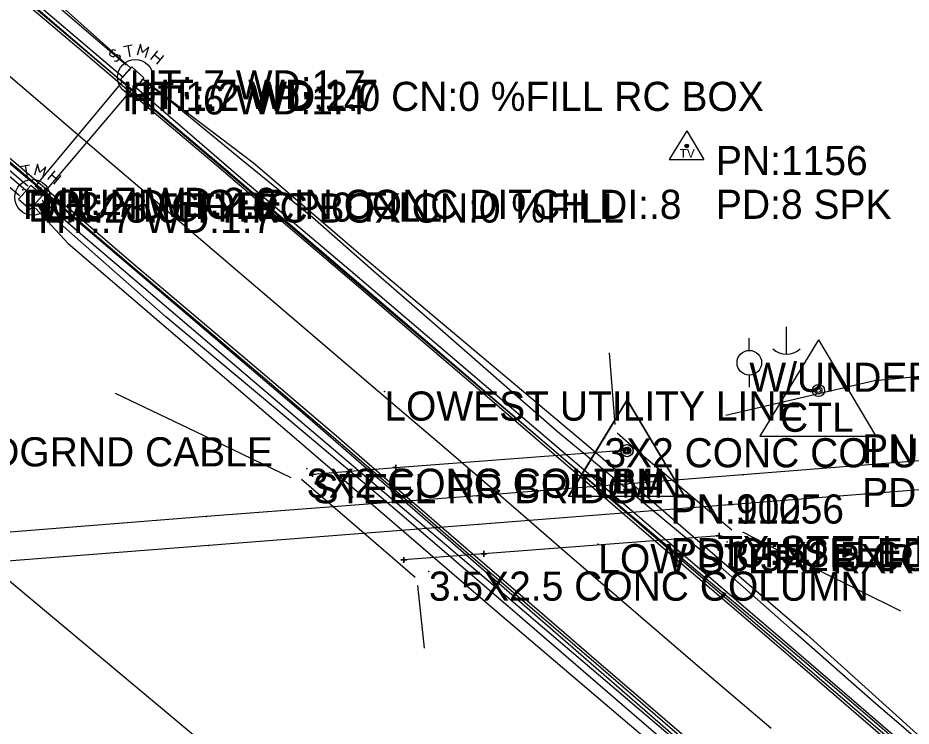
# Model space of a CAD drawing. Extents: x 878399 to 889864, y 1564003 to 1567413.
# Drawn here: x 884685 to 884838.2, y 1565440.6 to 1565562 of the extents above; entities that cross this region are included whole.
import ezdxf

# ---------------------------------------------------------------- set-up
doc = ezdxf.new("R2010")
doc.units = 0
for name, color, linetype in [('S_BRIDGE', 7, 'Continuous'), ('S_BRIDGE_ANNOT', 7, 'Continuous'), ('S_CATCH_BASIN_ANNOT', 7, 'Continuous'), ('S_CROSS_DRAIN', 7, 'Continuous'), ('S_CROSS_DRAIN_ANNOT', 7, 'Continuous'), ('S_DITCHLINE', 7, 'Continuous'), ('S_DRG_PT_SYM', 7, 'Continuous'), ('S_EDGE_CONCRETE', 7, 'Continuous'), ('S_EDGE_PAVEMENT', 7, 'Continuous'), ('S_ELECTRIC_UTILITIES_ANNOT', 7, 'Continuous'), ('S_FIBER_OPTIC_CABLE', 7, 'Continuous'), ('S_MISC_STRUCTURES_ANNOT', 7, 'Continuous'), ('S_MSC_PT_SYM', 7, 'Continuous'), ('S_PAVEMENT_CROWN', 7, 'Continuous'), ('S_PRIMARY_CTL', 7, 'Continuous'), ('S_PRIMARY_CTL_ANNOT', 7, 'Continuous'), ('S_RAILROAD', 7, 'Continuous'), ('S_SECONDARY_CTL', 7, 'Continuous'), ('S_SECONDARY_CTL_ANNOT', 7, 'Continuous'), ('S_SHOULDER', 7, 'Continuous'), ('S_STORM_SEWER', 7, 'Continuous'), ('S_STORM_SEWER_ANNOT', 7, 'Continuous'), ('S_STR_PT_SYM', 7, 'Continuous'), ('S_TELEPHONE_UTILITIES', 7, 'Continuous'), ('S_TELEPHONE_UTILITIES_ANNOT', 7, 'Continuous'), ('S_UTILITY_POLE', 7, 'Continuous'), ('S_UTL_PT_SYM', 7, 'Continuous'), ('S_WALL', 7, 'Continuous')]:
    doc.layers.add(name, color=color, linetype=linetype)

msp = doc.modelspace()

# ---------------------------------------------------------------- linework, layer by layer
at = {"layer": 'S_BRIDGE'}
for p, q in [((884749.84, 1565484.9), (884789.64, 1565487.95)), ((884735.58, 1565483.8), (884749.84, 1565484.9)), ((884805.3, 1565473.21), (884764.96, 1565470.14)), ((884764.96, 1565470.14), (884751.21, 1565469.07))]:
    msp.add_line(p, q, dxfattribs=at)
at = {"layer": 'S_CROSS_DRAIN'}
for p, q in [((884688.04, 1565533.14), (884702.96, 1565551.05)), ((884702.96, 1565551.05), (884704.57, 1565549.79)), ((884704.57, 1565549.79), (884689.4, 1565531.91)), ((884689.4, 1565531.91), (884688.04, 1565533.14))]:
    msp.add_line(p, q, dxfattribs=at)
at = {"layer": 'S_DITCHLINE'}
for points in [[(884703.6, 1565553.91), (884685.15, 1565569.81), (884674.64, 1565578.91)], [(884929.2, 1565361.71), (884912.86, 1565375.45), (884896.52, 1565389.2), (884880.31, 1565403.1), (884864.11, 1565417.01), (884847.9, 1565430.92), (884831.69, 1565444.83), (884818.34, 1565456.6), (884804.99, 1565468.36), (884791.26, 1565479.72), (884777.52, 1565491.09), (884767.03, 1565500.26), (884756.54, 1565509.43), (884746.04, 1565518.6), (884735.55, 1565527.77), (884723.63, 1565537.52), (884711.72, 1565547.27), (884706.92, 1565551.05)], [(884931.14, 1565322.32), (884915.28, 1565335.85), (884899.42, 1565349.39), (884882.54, 1565363.89), (884865.66, 1565378.39), (884848.78, 1565392.9), (884831.9, 1565407.4), (884813.4, 1565423.14), (884794.91, 1565438.87), (884783.2, 1565448.95), (884771.49, 1565459.02), (884759.78, 1565469.09), (884748.07, 1565479.17), (884729.25, 1565494.97), (884710.42, 1565510.77), (884693.84, 1565525.36), (884689.13, 1565529.56)], [(885174.2, 1565527.04), (885155.25, 1565525.71), (885136.3, 1565524.37), (885117.35, 1565523.04), (885098.4, 1565521.7), (885075.43, 1565519.72), (885052.47, 1565517.74), (885029.5, 1565515.76), (885006.54, 1565513.77), (884983.43, 1565512.24), (884960.32, 1565510.7), (884937.21, 1565509.17), (884914.1, 1565507.63), (884893.55, 1565505.67), (884873, 1565503.7), (884852.45, 1565501.74), (884831.9, 1565499.77), (884819.17, 1565496.81), (884806.44, 1565493.86)]]:
    msp.add_lwpolyline(points, dxfattribs=at)
at = {"layer": 'S_DRG_PT_SYM'}
for points in [[(884704.2, 1565553.02), (884704.2, 1565553.07), (884704.2, 1565553.02), (884704.15, 1565553.02), (884704.2, 1565553.02), (884704.2, 1565552.97), (884704.2, 1565553.02), (884704.25, 1565553.02)], [(884702.96, 1565551.05), (884702.96, 1565551.1), (884702.96, 1565551.05), (884702.91, 1565551.05), (884702.96, 1565551.05), (884702.96, 1565551), (884702.96, 1565551.05), (884703.01, 1565551.05)], [(884704.14, 1565550.45), (884704.14, 1565550.5), (884704.14, 1565550.45), (884704.08, 1565550.45), (884704.14, 1565550.45), (884704.14, 1565550.4), (884704.14, 1565550.45), (884704.19, 1565550.45)], [(884706.32, 1565551.39), (884706.32, 1565551.44), (884706.32, 1565551.39), (884706.27, 1565551.39), (884706.32, 1565551.39), (884706.32, 1565551.34), (884706.32, 1565551.39), (884706.37, 1565551.39)], [(884704.57, 1565549.79), (884704.57, 1565549.84), (884704.57, 1565549.79), (884704.51, 1565549.79), (884704.57, 1565549.79), (884704.57, 1565549.74), (884704.57, 1565549.79), (884704.61, 1565549.79)], [(884685.9, 1565532.54), (884685.9, 1565532.59), (884685.9, 1565532.54), (884685.85, 1565532.54), (884685.9, 1565532.54), (884685.9, 1565532.49), (884685.9, 1565532.54), (884685.95, 1565532.54)], [(884688.04, 1565533.14), (884688.04, 1565533.19), (884688.04, 1565533.14), (884687.99, 1565533.14), (884688.04, 1565533.14), (884688.04, 1565533.09), (884688.04, 1565533.14), (884688.09, 1565533.14)], [(884688.97, 1565532.88), (884688.97, 1565532.93), (884688.97, 1565532.88), (884688.92, 1565532.88), (884688.97, 1565532.88), (884688.97, 1565532.83), (884688.97, 1565532.88), (884689.02, 1565532.88)], [(884689.4, 1565531.91), (884689.4, 1565531.96), (884689.4, 1565531.91), (884689.35, 1565531.91), (884689.4, 1565531.91), (884689.4, 1565531.86), (884689.4, 1565531.91), (884689.45, 1565531.91)], [(884688.49, 1565530.11), (884688.49, 1565530.16), (884688.49, 1565530.11), (884688.44, 1565530.11), (884688.49, 1565530.11), (884688.49, 1565530.06), (884688.49, 1565530.11), (884688.54, 1565530.11)]]:
    msp.add_lwpolyline(points, dxfattribs=at)
at = {"layer": 'S_EDGE_CONCRETE'}
for points in [[(884323.93, 1565880.39), (884362.03, 1565848.01), (884400.08, 1565815.49), (884438.03, 1565782.92), (884475.84, 1565750.35), (884513.92, 1565717.85), (884552.01, 1565685.45), (884589.9, 1565652.9), (884627.72, 1565620.23), (884666.58, 1565587.18), (884704.34, 1565553.44)], [(884321.95, 1565878.07), (884359.86, 1565845.48), (884397.91, 1565812.97), (884436.05, 1565780.63), (884473.97, 1565748.16), (884511.98, 1565715.58), (884549.99, 1565683.11), (884587.82, 1565650.46), (884625.88, 1565618.07), (884664.43, 1565584.66), (884703.02, 1565551.9)], [(884515.49, 1565679.51), (884520.78, 1565674.96), (884543.23, 1565655.78), (884581.22, 1565623.28), (884619.31, 1565590.84), (884655, 1565560.28), (884686.74, 1565533.19)], [(884514.23, 1565678.05), (884518.85, 1565672.72), (884541.36, 1565653.58), (884579.74, 1565621.54), (884617.9, 1565589.19), (884653.7, 1565558.74), (884685.33, 1565531.53)], [(884706.6, 1565551.45), (884725.44, 1565537.13), (884744.17, 1565521.12), (884782.46, 1565488.91), (884820.33, 1565456.29), (884857.4, 1565422.83), (884893.19, 1565391.5), (884931.44, 1565358.94), (884969.96, 1565327.51), (885007.93, 1565294.95), (885045.65, 1565262.19), (885083.76, 1565229.98), (885121.86, 1565197.67), (885159.74, 1565165.3), (885198.19, 1565133.4), (885236.59, 1565102.25), (885296.12, 1565053.84), (885311.12, 1565043.35)], [(884705.4, 1565550.04), (884723.26, 1565534.58), (884742.1, 1565518.69), (884780.16, 1565486.23), (884818.14, 1565453.73), (884855.98, 1565421.17), (884892.08, 1565390.2), (884930.32, 1565357.68), (884968.08, 1565325.3), (885005.99, 1565292.69), (885044.06, 1565260.33), (885082.07, 1565227.99), (885120, 1565195.47), (885157.99, 1565163.2), (885196.4, 1565131.24), (885234.81, 1565099.94), (885295.36, 1565052.86), (885310.26, 1565042.23)], [(884689.18, 1565530.77), (884695.4, 1565525.38), (884733.42, 1565492.91), (884769.21, 1565462.51), (884807.31, 1565430.15), (884845.29, 1565397.58), (884883.12, 1565364.93), (884920.9, 1565332.67), (884959.15, 1565300.1), (884997.09, 1565267.66), (885035.26, 1565235.41), (885073.28, 1565202.9), (885111.19, 1565170.37), (885149.63, 1565138.23), (885187.82, 1565106.01), (885227.08, 1565074.25), (885266.64, 1565043.69), (885278.89, 1565034.31)], [(884688.03, 1565529.41), (884693.66, 1565523.34), (884731.61, 1565490.8), (884767.2, 1565460.17), (884805.29, 1565427.8), (884843.47, 1565395.44), (884881.16, 1565362.62), (884918.8, 1565330.29), (884957.02, 1565297.6), (884994.98, 1565265.2), (885032.99, 1565232.77), (885071.05, 1565200.29), (885109.01, 1565167.81), (885147.48, 1565135.65), (885185.66, 1565103.41), (885224.98, 1565071.52), (885264.55, 1565040.98), (885276.98, 1565031.83)]]:
    msp.add_lwpolyline(points, dxfattribs=at)
for points in [[(884704.78, 1565549.49), (884702.65, 1565551.39), (884704.56, 1565553.59), (884706.65, 1565551.72)], [(884689.24, 1565531.58), (884687.27, 1565533.25), (884685.15, 1565530.92), (884687.17, 1565529.21)]]:
    msp.add_lwpolyline(points, close=True, dxfattribs=at)
at = {"layer": 'S_EDGE_PAVEMENT'}
for points in [[(884673.76, 1565575.86), (884685.2, 1565566.15), (884696.63, 1565556.44), (884708.06, 1565546.72), (884719.51, 1565537.03), (884730.93, 1565527.29), (884742.33, 1565517.55), (884753.72, 1565507.79), (884765.12, 1565498.04), (884776.53, 1565488.26), (884787.91, 1565478.49), (884799.29, 1565468.72), (884810.66, 1565458.95), (884822.04, 1565449.18), (884833.38, 1565439.44), (884844.76, 1565429.68), (884856.14, 1565419.92), (884867.5, 1565410.14), (884878.86, 1565400.36), (884890.22, 1565390.58), (884901.62, 1565380.84), (884913.16, 1565370.98), (884924.56, 1565361.24)], [(884684.78, 1565565.87), (884696.21, 1565556.16), (884707.64, 1565546.44), (884719.09, 1565536.75), (884730.51, 1565527.01), (884741.91, 1565517.27), (884753.31, 1565507.51), (884764.7, 1565497.76), (884776.12, 1565487.98), (884787.5, 1565478.21), (884798.87, 1565468.44), (884810.25, 1565458.67), (884821.62, 1565448.9), (884832.97, 1565439.16), (884844.35, 1565429.4), (884855.73, 1565419.63), (884867.09, 1565409.85), (884878.45, 1565400.07), (884889.81, 1565390.29), (884901.21, 1565380.55), (884912.75, 1565370.69), (884924.15, 1565360.95)], [(884681.61, 1565539.03), (884693.05, 1565529.33), (884704.45, 1565519.58), (884715.9, 1565509.89), (884727.36, 1565500.21), (884738.77, 1565490.47), (884750.12, 1565480.67), (884761.46, 1565470.88), (884772.81, 1565461.08), (884784.18, 1565451.3), (884795.55, 1565441.52), (884806.91, 1565431.74), (884818.31, 1565421.91), (884829.66, 1565412.11), (884841.01, 1565402.32), (884852.37, 1565392.52), (884863.72, 1565382.73), (884875.07, 1565372.95), (884886.44, 1565363.18), (884897.65, 1565353.64), (884909.07, 1565343.93), (884920.49, 1565334.22)], [(884682.03, 1565539.31), (884693.47, 1565529.6), (884704.87, 1565519.86), (884716.32, 1565510.17), (884727.78, 1565500.49), (884739.19, 1565490.75), (884750.54, 1565480.95), (884761.87, 1565471.16), (884773.23, 1565461.36), (884784.59, 1565451.58), (884795.96, 1565441.8), (884807.33, 1565432.02), (884818.72, 1565422.19), (884830.07, 1565412.4), (884841.43, 1565402.6), (884852.78, 1565392.81), (884864.13, 1565383.02), (884875.48, 1565373.23), (884886.85, 1565363.46), (884898.06, 1565353.93), (884909.48, 1565344.22), (884920.89, 1565334.51)]]:
    msp.add_lwpolyline(points, dxfattribs=at)
at = {"layer": 'S_FIBER_OPTIC_CABLE'}
msp.add_line((884746.2, 1565413.17), (884630.03, 1565510.1), dxfattribs=at)
at = {"layer": 'S_MSC_PT_SYM'}
for points in [[(884785.6, 1565489.95), (884785.6, 1565490), (884785.6, 1565489.95), (884785.55, 1565489.95), (884785.6, 1565489.95), (884785.6, 1565489.9), (884785.6, 1565489.95), (884785.65, 1565489.95)], [(884734.59, 1565484.73), (884734.59, 1565484.78), (884734.59, 1565484.73), (884734.54, 1565484.73), (884734.59, 1565484.73), (884734.59, 1565484.68), (884734.59, 1565484.73), (884734.64, 1565484.73)], [(884809.34, 1565483.69), (884809.34, 1565483.74), (884809.34, 1565483.69), (884809.29, 1565483.69), (884809.34, 1565483.69), (884809.34, 1565483.64), (884809.34, 1565483.69), (884809.39, 1565483.69)], [(884763.8, 1565480.08), (884763.8, 1565480.13), (884763.8, 1565480.08), (884763.75, 1565480.08), (884763.8, 1565480.08), (884763.8, 1565480.03), (884763.8, 1565480.08), (884763.85, 1565480.08)], [(884809.99, 1565478.75), (884809.99, 1565478.8), (884809.99, 1565478.75), (884809.94, 1565478.75), (884809.99, 1565478.75), (884809.99, 1565478.7), (884809.99, 1565478.75), (884810.04, 1565478.75)], [(884717.39, 1565476.51), (884717.39, 1565476.56), (884717.39, 1565476.51), (884717.34, 1565476.51), (884717.39, 1565476.51), (884717.39, 1565476.46), (884717.39, 1565476.51), (884717.44, 1565476.51)], [(884763.99, 1565475.18), (884763.99, 1565475.23), (884763.99, 1565475.18), (884763.94, 1565475.18), (884763.99, 1565475.18), (884763.99, 1565475.13), (884763.99, 1565475.18), (884764.04, 1565475.18)], [(884806.66, 1565472.18), (884806.66, 1565472.23), (884806.66, 1565472.18), (884806.61, 1565472.18), (884806.66, 1565472.18), (884806.66, 1565472.13), (884806.66, 1565472.18), (884806.71, 1565472.18)], [(884717.78, 1565471.58), (884717.78, 1565471.63), (884717.78, 1565471.58), (884717.73, 1565471.58), (884717.78, 1565471.58), (884717.78, 1565471.53), (884717.78, 1565471.58), (884717.83, 1565471.58)], [(884784.56, 1565471.79), (884784.56, 1565471.84), (884784.56, 1565471.79), (884784.51, 1565471.79), (884784.56, 1565471.79), (884784.56, 1565471.74), (884784.56, 1565471.79), (884784.61, 1565471.79)], [(884755.52, 1565467.09), (884755.52, 1565467.14), (884755.52, 1565467.09), (884755.47, 1565467.09), (884755.52, 1565467.09), (884755.52, 1565467.04), (884755.52, 1565467.09), (884755.57, 1565467.09)]]:
    msp.add_lwpolyline(points, dxfattribs=at)
at = {"layer": 'S_PAVEMENT_CROWN'}
msp.add_lwpolyline([(884677.44, 1565557.27), (884688.85, 1565547.53), (884688.85, 1565547.53), (884700.26, 1565537.79), (884711.67, 1565528.05), (884711.67, 1565528.05), (884723.08, 1565518.31), (884734.49, 1565508.57), (884745.91, 1565498.84), (884757.32, 1565489.1), (884757.32, 1565489.1), (884768.69, 1565479.32), (884780.05, 1565469.52), (884791.41, 1565459.73), (884802.78, 1565449.96), (884814.18, 1565440.22)], dxfattribs=at)
at = {"layer": 'S_PRIMARY_CTL'}
for p, q in [((884822.31, 1565506.83), (884812.28, 1565490.32)), ((884822.31, 1565506.83), (884832.14, 1565490.32)), ((884789.45, 1565496.51), (884779.42, 1565479.99)), ((884789.53, 1565496.52), (884779.49, 1565480.01)), ((884789.45, 1565496.51), (884799.28, 1565479.99)), ((884789.53, 1565496.52), (884799.35, 1565480.01)), ((884812.28, 1565490.32), (884832.14, 1565490.32)), ((884779.42, 1565479.99), (884799.28, 1565479.99)), ((884779.49, 1565480.01), (884799.35, 1565480.01))]:
    msp.add_line(p, q, dxfattribs=at)
for centre, radius in [((884822.31, 1565498.13), 1.04), ((884822.31, 1565498.13), 0.609), ((884822.31, 1565498.13), 0.344), ((884789.45, 1565487.81), 1.04), ((884789.53, 1565487.82), 1.04), ((884789.45, 1565487.81), 0.609), ((884789.53, 1565487.82), 0.609), ((884789.45, 1565487.81), 0.344), ((884789.53, 1565487.82), 0.344)]:
    msp.add_circle(centre, radius, dxfattribs=at)
at = {"layer": 'S_RAILROAD'}
for p, q in [((884860, 1565487.69), (884809.34, 1565483.69)), ((884809.34, 1565483.69), (884763.8, 1565480.08)), ((884860.76, 1565482.78), (884809.99, 1565478.75)), ((884763.8, 1565480.08), (884717.39, 1565476.51)), ((884809.99, 1565478.75), (884763.99, 1565475.18)), ((884717.39, 1565476.51), (884681.18, 1565473.66)), ((884763.99, 1565475.18), (884717.78, 1565471.58)), ((884717.78, 1565471.58), (884681.7, 1565468.75))]:
    msp.add_line(p, q, dxfattribs=at)
at = {"layer": 'S_SECONDARY_CTL'}
for p, q in [((884799.74, 1565542.66), (884796.73, 1565537.71)), ((884799.74, 1565542.66), (884802.69, 1565537.71)), ((884796.73, 1565537.71), (884802.69, 1565537.71))]:
    msp.add_line(p, q, dxfattribs=at)
for radius in [0.311, 0.183, 0.103]:
    msp.add_circle((884799.74, 1565540.05), radius, dxfattribs=at)
at = {"layer": 'S_SHOULDER'}
for points in [[(884315.55, 1565882.9), (884321.54, 1565877.6), (884359.45, 1565845), (884397.59, 1565812.6), (884435.73, 1565780.26), (884473.65, 1565747.79), (884511.66, 1565715.22), (884549.66, 1565682.72), (884587.52, 1565650.1), (884625.56, 1565617.69), (884664.18, 1565584.36), (884702.58, 1565551.39), (884704.78, 1565549.31), (884722.81, 1565534.04), (884741.48, 1565517.97), (884779.63, 1565485.61), (884817.88, 1565453.42), (884855.77, 1565420.91), (884891.75, 1565389.81), (884929.91, 1565357.22)], [(884655.38, 1565560.72), (884687.38, 1565533.95), (884690.03, 1565531.77), (884696.22, 1565526.35), (884734.31, 1565493.96), (884769.75, 1565463.15), (884807.48, 1565430.34), (884845.42, 1565397.74), (884883.27, 1565365.1), (884921.11, 1565332.91)]]:
    msp.add_lwpolyline(points, dxfattribs=at)
at = {"layer": 'S_STORM_SEWER'}
for p, q in [((884686.78, 1565532.07), (884514.98, 1565679.93)), ((884701.39, 1565556.51), (884700.85, 1565556.12)), ((884701.81, 1565556.43), (884701.39, 1565556.51)), ((884703.13, 1565557.09), (884704.64, 1565557.36)), ((884703.91, 1565557.25), (884704.26, 1565555.31)), ((884707.82, 1565554.88), (884709.06, 1565556.36)), ((884700.85, 1565556.12), (884700.77, 1565555.74)), ((884700.77, 1565555.74), (884700.96, 1565555.47)), ((884700.96, 1565555.47), (884701.39, 1565555.35)), ((884701.39, 1565555.35), (884701.93, 1565555.7)), ((884701.93, 1565555.7), (884702.4, 1565555.62)), ((884702.47, 1565554.92), (884701.93, 1565554.54)), ((884702.4, 1565555.62), (884702.55, 1565555.35)), ((884702.55, 1565555.35), (884702.47, 1565554.92)), ((884708.48, 1565555.66), (884709.45, 1565554.85)), ((884710.03, 1565555.54), (884708.79, 1565554.07)), ((884701.93, 1565554.54), (884701.54, 1565554.61)), ((884685.5, 1565536.53), (884687.01, 1565536.8)), ((884686.27, 1565536.68), (884686.62, 1565534.74)), ((884690.19, 1565534.32), (884691.43, 1565535.79)), ((884690.85, 1565535.09), (884691.82, 1565534.28)), ((884692.4, 1565534.98), (884691.16, 1565533.5))]:
    msp.add_line(p, q, dxfattribs=at)
for points in [[(884706.93, 1565555.19), (884707.47, 1565557.05), (884706.43, 1565556.05), (884706.04, 1565557.48), (884705.5, 1565555.62)], [(884689.3, 1565534.63), (884689.84, 1565536.49), (884688.79, 1565535.48), (884688.41, 1565536.91), (884687.86, 1565535.05)]]:
    msp.add_lwpolyline(points, dxfattribs=at)
for centre in [(884705.17, 1565551.82), (884687.54, 1565531.25)]:
    msp.add_circle(centre, 3.05, dxfattribs=at)
at = {"layer": 'S_STR_PT_SYM'}
for points in [[(884789.64, 1565487.95), (884789.64, 1565488.45), (884789.64, 1565487.95), (884789.14, 1565487.95), (884789.64, 1565487.95), (884789.64, 1565487.45), (884789.64, 1565487.95), (884790.14, 1565487.95)], [(884749.84, 1565484.9), (884749.84, 1565485.4), (884749.84, 1565484.9), (884749.34, 1565484.9), (884749.84, 1565484.9), (884749.84, 1565484.4), (884749.84, 1565484.9), (884750.34, 1565484.9)], [(884735.58, 1565483.8), (884735.58, 1565484.3), (884735.58, 1565483.8), (884735.08, 1565483.8), (884735.58, 1565483.8), (884735.58, 1565483.3), (884735.58, 1565483.8), (884736.08, 1565483.8)], [(884805.3, 1565473.21), (884805.3, 1565473.71), (884805.3, 1565473.21), (884804.8, 1565473.21), (884805.3, 1565473.21), (884805.3, 1565472.71), (884805.3, 1565473.21), (884805.8, 1565473.21)], [(884764.96, 1565470.14), (884764.96, 1565470.64), (884764.96, 1565470.14), (884764.46, 1565470.14), (884764.96, 1565470.14), (884764.96, 1565469.64), (884764.96, 1565470.14), (884765.46, 1565470.14)], [(884751.21, 1565469.07), (884751.21, 1565469.57), (884751.21, 1565469.07), (884750.71, 1565469.07), (884751.21, 1565469.07), (884751.21, 1565468.57), (884751.21, 1565469.07), (884751.71, 1565469.07)]]:
    msp.add_lwpolyline(points, dxfattribs=at)
at = {"layer": 'S_TELEPHONE_UTILITIES'}
for p, q in [((884810.43, 1565504.97), (884810.43, 1565507.1)), ((884810.43, 1565500.75), (884810.43, 1565498.7))]:
    msp.add_line(p, q, dxfattribs=at)
msp.add_circle((884810.46, 1565502.89), 2.11, dxfattribs=at)
at = {"layer": 'S_UTILITY_POLE'}
msp.add_line((884816.77, 1565509.06), (884816.77, 1565504.33), dxfattribs=at)
msp.add_arc((884816.83, 1565507.76), 3.41, 226.3972, 313.6028, dxfattribs=at)
at = {"layer": 'S_UTL_PT_SYM'}
for points in [[(884705.09, 1565551.78), (884705.09, 1565551.83), (884705.09, 1565551.78), (884705.04, 1565551.78), (884705.09, 1565551.78), (884705.09, 1565551.73), (884705.09, 1565551.78), (884705.14, 1565551.78)], [(884686.78, 1565532.07), (884686.78, 1565532.12), (884686.78, 1565532.07), (884686.73, 1565532.07), (884686.78, 1565532.07), (884686.78, 1565532.02), (884686.78, 1565532.07), (884686.83, 1565532.07)], [(884687.68, 1565531.36), (884687.68, 1565531.41), (884687.68, 1565531.36), (884687.63, 1565531.36), (884687.68, 1565531.36), (884687.68, 1565531.31), (884687.68, 1565531.36), (884687.73, 1565531.36)], [(884747.88, 1565497.96), (884747.88, 1565498.01), (884747.88, 1565497.96), (884747.83, 1565497.96), (884747.88, 1565497.96), (884747.88, 1565497.91), (884747.88, 1565497.96), (884747.93, 1565497.96)]]:
    msp.add_lwpolyline(points, dxfattribs=at)
at = {"layer": 'S_WALL'}
for points in [[(884787.48, 1565492.29), (884786.48, 1565504.57)], [(884731.9, 1565483.17), (884716.84, 1565490.39), (884701.78, 1565497.61)], [(884787.8, 1565490.87), (884792.06, 1565487.12), (884807.46, 1565474.22)], [(884733.69, 1565482.95), (884749.32, 1565469.43), (884753.14, 1565466.15)], [(884809.28, 1565473.9), (884815.06, 1565470.92), (884836.39, 1565460.38)], [(884754.74, 1565453.94), (884753.64, 1565464.71)]]:
    msp.add_lwpolyline(points, dxfattribs=at)

# ---------------------------------------------------------------- texts
at = {"layer": 'S_BRIDGE_ANNOT'}
for s, p in [('STEEL RR BRIDGE', (884735.58, 1565478.8)), ('TY:STEEL RR RR BRIDGE', (884805.3, 1565468.21))]:
    msp.add_text(s, height=5, dxfattribs=at).set_placement(p)
at = {"layer": 'S_CATCH_BASIN_ANNOT'}
for s, p in [('HT:.7 WD:1.7', (884704.2, 1565548.02)), ('HT:.6 WD:1.4', (884704.14, 1565545.45)), ('HT:.7 WD:1.7', (884706.32, 1565546.39)), ('ROUND HOLE IN CONC DITCH DI:.8', (884685.9, 1565527.54)), ('HT:.7 WD:2.0', (884688.97, 1565527.88)), ('HT:.7 WD:1.7', (884688.49, 1565525.11))]:
    msp.add_text(s, height=5, dxfattribs=at).set_placement(p)
at = {"layer": 'S_CROSS_DRAIN_ANNOT'}
for s, p in [('HT:1.2 WD:2.0 CN:0 %FILL RC BOX', (884702.96, 1565546.05)), ('LN:23.5 TY:RC BOX CN:0 %FILL', (884689.4, 1565526.91))]:
    msp.add_text(s, height=5, dxfattribs=at).set_placement(p)
at = {"layer": 'S_ELECTRIC_UTILITIES_ANNOT'}
msp.add_text('LOWEST UTILITY LINE', height=5, dxfattribs=at).set_placement((884747.88, 1565492.96))
at = {"layer": 'S_MISC_STRUCTURES_ANNOT'}
for s, p in [('3X2 CONC COLUMN', (884785.6, 1565484.95)), ('3X2 CONC COLUMN', (884734.59, 1565479.73)), ('3.5X2.5 CONC COLUMN', (884806.66, 1565467.18)), ('LOW STEEL RXR BR 14.5 ABOVE HWY 82', (884784.56, 1565466.79)), ('3.5X2.5 CONC COLUMN', (884755.52, 1565462.09))]:
    msp.add_text(s, height=5, dxfattribs=at).set_placement(p)
at = {"layer": 'S_PRIMARY_CTL'}
for s, height, p in [('CTL', 5, (884815.73, 1565491.05)), ('TBM', 4.287, (884783.8, 1565480.42)), ('TBM', 4.287, (884783.87, 1565480.43))]:
    msp.add_text(s, height=height, rotation=360, dxfattribs=at).set_placement(p)
at = {"layer": 'S_PRIMARY_CTL_ANNOT'}
for s, p in [('PN:4', (884829.81, 1565485.63)), ('PD:ARDOT STD. MON. STAMPED PN:4', (884829.81, 1565478.13)), ('PN:11056', (884796.95, 1565475.31)), ('PN:902', (884797.03, 1565475.32)), ('PD:', (884796.95, 1565467.81)), ('PD:CHISELED SQUARE', (884797.03, 1565467.82))]:
    msp.add_text(s, height=5, dxfattribs=at).set_placement(p)
at = {"layer": 'S_SECONDARY_CTL'}
msp.add_text('TV', height=1.5, rotation=360, dxfattribs=at).set_placement((884798.54, 1565538.04))
at = {"layer": 'S_SECONDARY_CTL_ANNOT'}
for s, p in [('PN:1156', (884804.74, 1565535.05)), ('PD:8 SPK', (884804.74, 1565527.55))]:
    msp.add_text(s, height=5, dxfattribs=at).set_placement(p)
at = {"layer": 'S_STORM_SEWER_ANNOT'}
msp.add_text('DI:24 INCH RCP 0 FILL', height=5, dxfattribs=at).set_placement((884686.78, 1565527.07))
at = {"layer": 'S_TELEPHONE_UTILITIES_ANNOT'}
for s, p in [('W/UNDERGR CABLE', (884810.46, 1565497.9)), ('UNDGRND CABLE', (884670.81, 1565485.11))]:
    msp.add_text(s, height=5, dxfattribs=at).set_placement(p)

doc.saveas('drawing.dxf')
